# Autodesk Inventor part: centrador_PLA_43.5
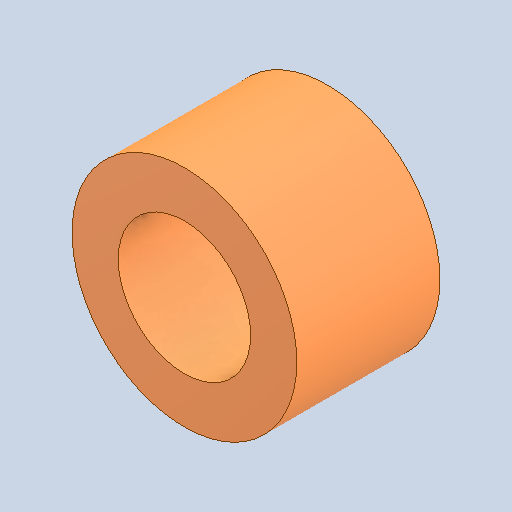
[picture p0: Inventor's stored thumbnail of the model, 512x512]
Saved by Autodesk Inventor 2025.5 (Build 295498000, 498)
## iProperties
Created: 2026-10
Part Number: centrador_PLA_43.5
Material: Genérico
Document SubType Name: Modeling
Designer: Luis M
Density: 1 g/cm^3
Appearance: Valor por defecto
Author: Luis M
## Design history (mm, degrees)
feature "Base1"
node "Sólido1"
